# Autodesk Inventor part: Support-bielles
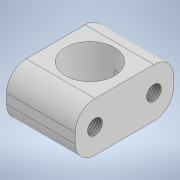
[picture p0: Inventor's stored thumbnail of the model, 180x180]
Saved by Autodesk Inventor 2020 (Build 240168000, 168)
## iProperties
Created: 2023-10
Part Number: Support-bielles
Material: Générique
Document SubType Name: Modeling
Designer: bruno
Density: 1 g/cm^3
Appearance: Par défaut
Author: bruno
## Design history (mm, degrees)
sketch "Esquisse1"
  geometry: L1 (4, 0)-(6, 0); L2 (10, -4)-(10, -16); L3 (6, -20)-(4, -20); L4 (0, -16)-(0, -4); A1 r 4 centre (6, -4) between (10, -4) and (6, 0); A2 r 4 centre (4, -4) between (4, 0) and (0, -4); A3 r 4 centre (4, -16) between (0, -16) and (4, -20); A4 r 4 centre (6, -16) between (6, -20) and (10, -16); 4 further points
  constraints: 8 end point, 8 point on circle, 8 point on line, 8 tangent, 4 centre point, 3 equal radius, 2 parallel, 1 horizontal, 1 perpendicular
  dimensions: "d0" = 10 distance of point (10, -20) point (0, -20); "d1" = 20 distance of point (10, 0) point (10, -20); "d2" = 4 radius of A1
extrude "Extrusion1" new body sketch "Esquisse1" distance "d3" = 14; taper "d4" = 0 deg
sketch "Esquisse2"
  geometry: L1 (0, 12)-(0, 0) reference; L2 (14, 12)-(14, 0) reference; L3 (0, 0)-(14, 12); C1 r 5 at (7, 6); 1 further point
  constraints: 2 end point, 1 centre point, 1 midpoint
  dimensions: "d5" = 10 diameter of C1
extrude "Extrusion2" cut sketch "Esquisse2" distance "d6" = 14; taper "d7" = 0 deg
sketch "Esquisse3"
  geometry: L1 (4, 0)-(16, 0) reference; L2 (20, 4)-(20, 6) reference; L3 (16, 10)-(4, 10) reference; L4 (0, 6)-(0, 4) reference; L5 (0, 5)-(20, 5); L6 (20, 4)-(20, 6) reference; C1 r 1.5 at (4, 5); C2 r 1.5 at (16, 5); A1 r 4 centre (4, 4) between (0, 4) and (4, 0) reference; A2 r 4 centre (16, 4) between (16, 0) and (20, 4) reference; A3 r 4 centre (16, 6) between (20, 6) and (16, 10) reference; A4 r 4 centre (4, 6) between (4, 10) and (0, 6) reference; 1 further point
  constraints: 2 centre point, 2 end point, 2 midpoint, 2 point on line
  dimensions: "d8" = 3 diameter of C1; "d9" = 4 distance from line of L4 C1.centre; "d10" = 3 diameter of C2; "d11" = 4 distance from line of L2 C2.centre
extrude "Extrusion3" cut sketch "Esquisse3" distance "d12" = 7; taper "d13" = 0 deg
feature "Filetage1" dims "d14" = 10, "d15" = 0
feature "Filetage2" dims "d16" = 10, "d17" = 0
node "Solide1"
node "Boucle projetée1"
